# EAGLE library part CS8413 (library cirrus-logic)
96 kHz Digital Audio Receiver Source: http://www.cirrus.com/en/pubs/proDatasheet/8413-4.pdf
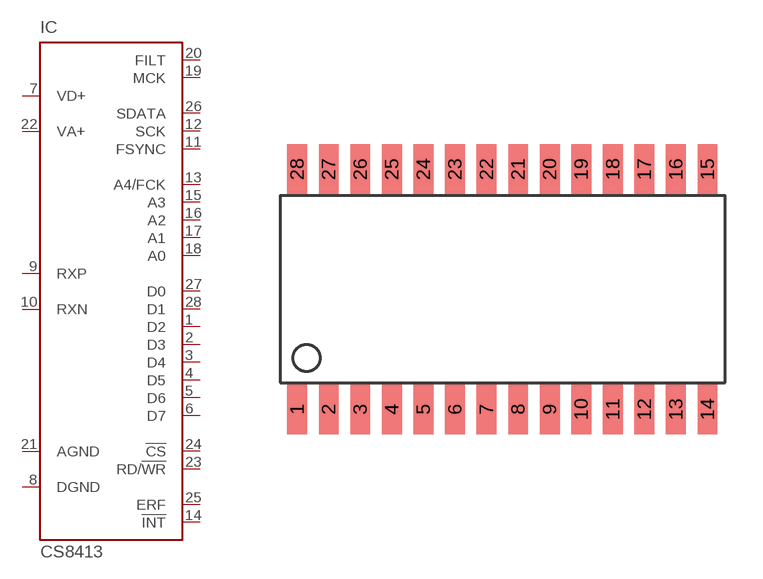
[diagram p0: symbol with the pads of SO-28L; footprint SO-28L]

Designator prefix IC

## CS8413 (MF: CIRRUS LOGIC; MPN: CS8413CS; OC_FARNELL: unknown; OC_NEWARK: 73C6130)  [SO-28L]
1  D2
2  D3
3  D4
4  D5
5  D6
6  D7
7  VD+  pwr
8  DGND  pwr
9  RXP  in
10  RXN  in
11  FSYNC
12  SCK
13  A4/FCK  in
14  !INT  out
15  A3  in
16  A2  in
17  A1  in
18  A0  in
19  MCK
20  FILT  out
21  AGND  pwr
22  VA+  in
23  RD/!WR  in
24  !CS  in
25  ERF  out
26  SDATA  out
27  D0
28  D1

## Footprint SO-28L (pad centres in mm)
Small Outline large
smd 0.8 x 2: 1 -8.255,-4.826; 2 -6.985,-4.826; 3 -5.715,-4.826; 4 -4.445,-4.826; 5 -3.175,-4.826; 6 -1.905,-4.826; 7 -0.635,-4.826; 8 0.635,-4.826; 9 1.905,-4.826; 10 3.175,-4.826; 11 4.445,-4.826; 12 5.715,-4.826; 13 6.985,-4.826; 14 8.255,-4.826; 15 8.255,4.826; 16 6.985,4.826; 17 5.715,4.826; 18 4.445,4.826; 19 3.175,4.826; 20 1.905,4.826; 21 0.635,4.826; 22 -0.635,4.826; 23 -1.905,4.826; 24 -3.175,4.826; 25 -4.445,4.826; 26 -5.715,4.826; 27 -6.985,4.826; 28 -8.255,4.826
